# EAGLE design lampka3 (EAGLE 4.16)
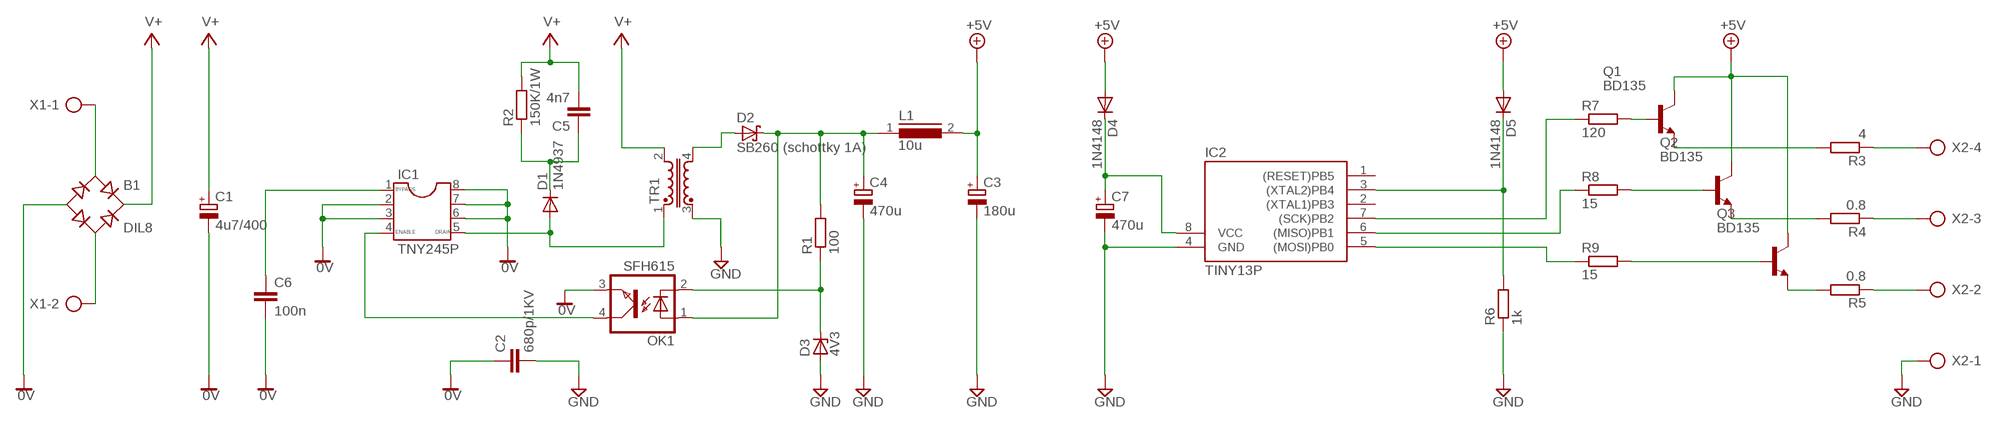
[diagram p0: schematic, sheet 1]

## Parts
B1  DIL8  B-DIL  [B-DIL]
C1  4u7/400  CPOL-EUE5-10.5  [E5-10,5]
C2  680p/1KV  C-EU102-043X133  [C102-043X133]
C3  180u  CPOL-EUE2.5-6  [E2,5-6]
C4  470u  CPOL-EUE3.5-8  [E3,5-8]
C5  4n7  C-EU050-025X075  [C050-025X075]
C6  100n  C-EU050-024X044  [C050-024X044]
C7  470u  CPOL-EUE2.5-7  [E2,5-7]
D1  1N4937  1N4933  [DO41-10]
D2  SB260 (schottky 1A)  SCHOTTKY-DIODEF126Z12  [F126Z12]
D3  4V3  ZENER-DIODEDO35Z10  [DO35Z10]
D4  1N4148  [DO35-10]
D5  1N4148  [DO35-10]
IC1  TNY245P  DIL8  [DIL08]
IC2  TINY13P  TINY12P  [DIL08]
L1  10u  82114R  [82114R]
OK1  SFH615  [DIL04]
Q1  BD135  BD139  [TO126]
Q2  BD135  BD139  [TO126]
Q3  BD135  BD139  [TO126]
R1  100  R-EU_0207/10  [0207/10]
R2  150K/1W  R-EU_0411/12  [0411/12]
R3  4  R-EU_0411/12  [0411/12]
R4  0.8  R-EU_0411/12  [0411/12]
R5  0.8  R-EU_0411/12  [0411/12]
R6  1k  R-EU_0207/10  [0207/10]
R7  120  R-EU_0207/10  [0207/10]
R8  15  R-EU_0207/10  [0207/10]
R9  15  R-EU_0207/10  [0207/10]
TR1  U15-TRANSFORMER  [U15]
X1  AK500/2  [AK500/2]
X2  AK500/4  [AK500/4]

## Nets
0V: B1.- C1.- C2.1 C6.2 IC1.2 IC1.3 IC1.6 IC1.7 IC1.8 OK1.3(EMIT)
+5V: C3.+ D4.A D5.A L1.2 Q1.2(C) Q2.2(C) Q3.2(C)
GND: C2.2 C3.- C4.- C7.- D3.A IC2.4(GND) R6.1 TR1.3 X2.1
N$1: B1.AC1 X1.1
N$2: B1.AC2 X1.2
N$3: C6.1 IC1.1
N$4: IC1.4 OK1.4(COL)
N$5: D1.A IC1.5 TR1.1
N$6: C5.1 D1.C R2.1
N$7: D2.A TR1.4
N$8: C4.+ D2.C L1.1 OK1.1(A) R1.2
N$9: D3.C OK1.2(C) R1.1
N$11: D5.C IC2.3((XTAL2)PB4) R6.2
N$12: IC2.5((MOSI)PB0) R9.1
N$13: IC2.6((MISO)PB1) R8.1
N$14: IC2.7((SCK)PB2) R7.1
N$15: Q1.3(B) R7.2
N$16: Q2.3(B) R8.2
N$17: Q3.3(B) R9.2
N$19: R5.1 X2.2
N$20: Q1.1(E) R3.2
N$21: Q2.1(E) R4.2
N$22: Q3.1(E) R5.2
N$23: C7.+ D4.C IC2.8(VCC)
N$24: R4.1 X2.3
N$25: R3.1 X2.4
V+: B1.+ C1.+ C5.2 R2.2 TR1.2
Unconnected: IC2.1((RESET)PB5) IC2.2((XTAL1)PB3)

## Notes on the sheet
- BYPASS
- ENABLE | DRAIN

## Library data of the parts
B1 = rectifier:B-DIL: RECTIFIER
C1 C3 C4 C7 = rcl:CPOL-EU: POLARIZED CAPACITOR, European symbol
C2 C5 C6 = rcl:C-EU: CAPACITOR, European symbol
D1 = diode:1N4933: DIODE
D2 = diode:SCHOTTKY-DIODE: Schottky Diode
D3 = diode:ZENER-DIODE: Z-Diode
D4 D5 = diode:1N4148: DIODE
IC1 = ic-package:DIL8: Dual In Line
IC2 = atmel:TINY12*: MICROCONTROLLER 1 Kbytes FLASH 64 bytes EEPROM
L1 = inductors:82114R: INDUCTOR
OK1 = optocoupler:SFH615: SIEMENS OPTO COUPLER
Q1-Q3 = transistor-npn:BD139*: NPN Transistor
R1-R9 = rcl:R-EU_: RESISTOR, European symbol
TR1 = inductor-neosid2:U15: TRANSFORMER U15
X1 = con-ptr500:AK500/2: CONNECTOR
X2 = con-ptr500:AK500/4: CONNECTOR

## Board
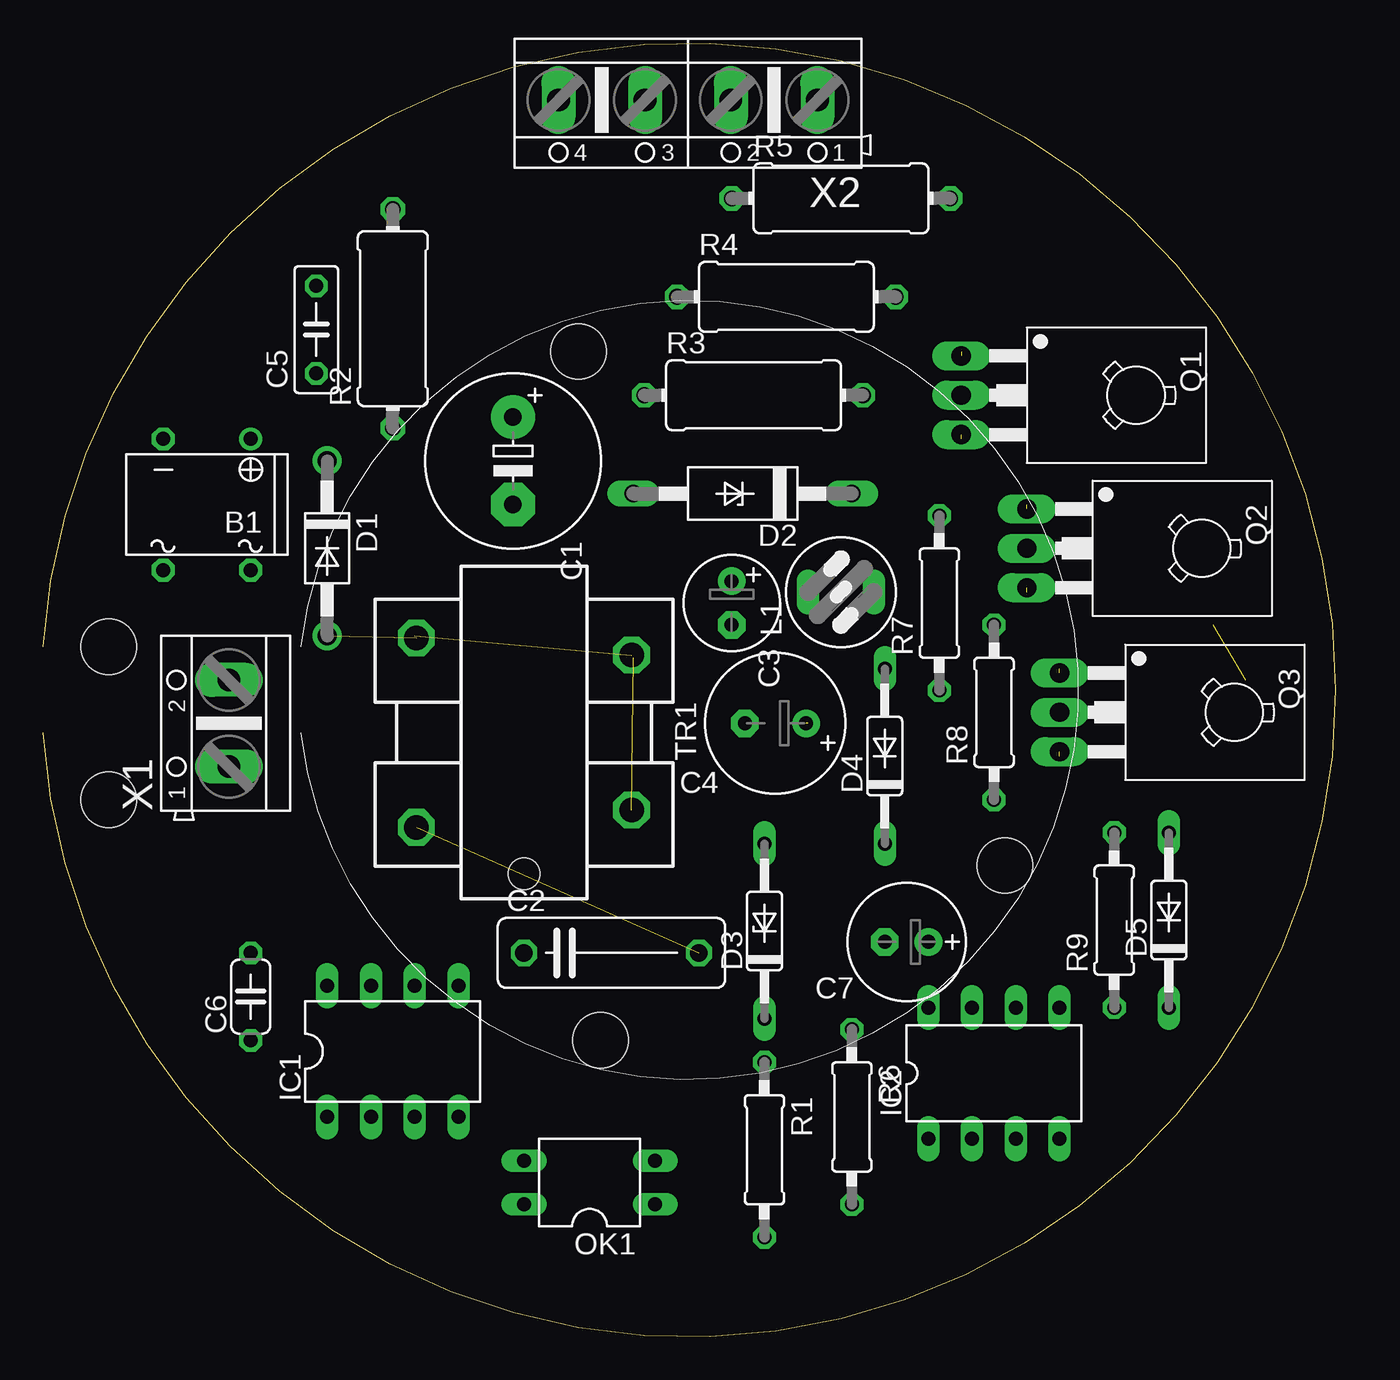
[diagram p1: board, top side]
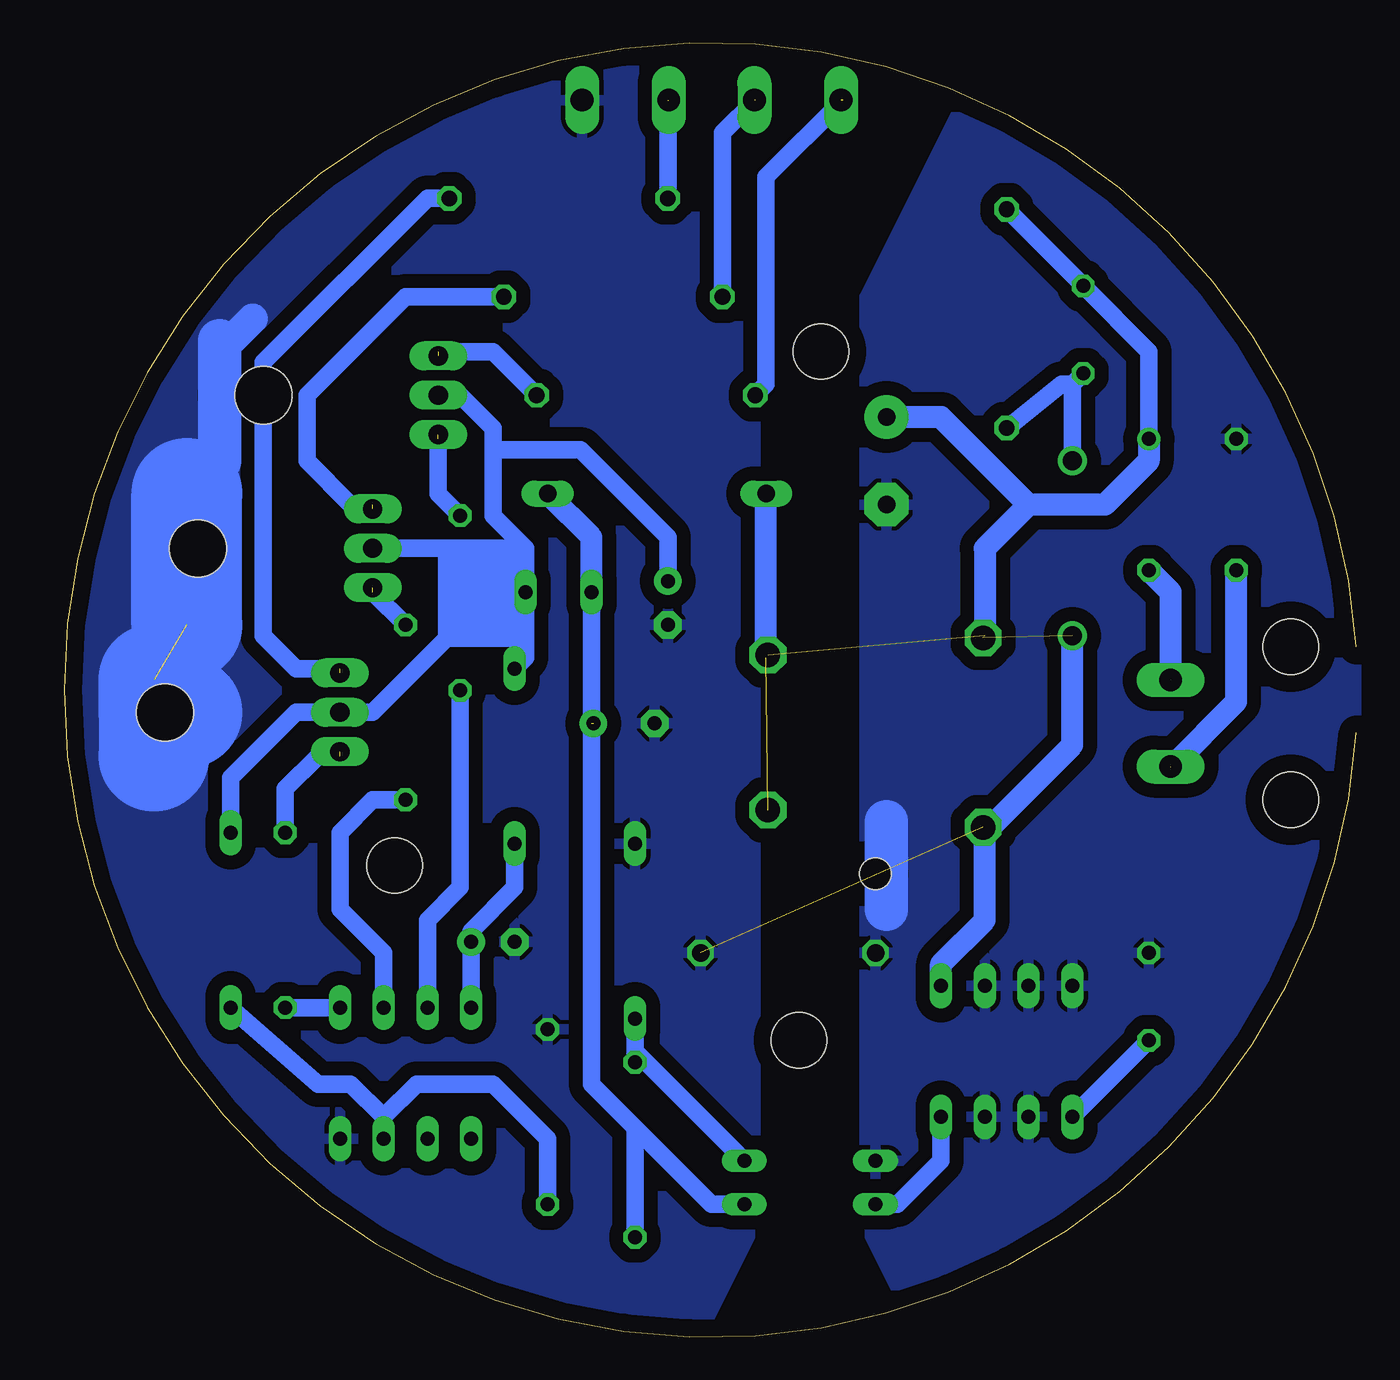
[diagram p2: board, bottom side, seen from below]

Size 75.08 x 75.13 mm. Coordinates in mm from the lower left corner, seen from the top.
Outline: 0,40.06 arc-352 0,35.06
Copper layers (1*16): Top 0.035mm / dielectric 1.5mm / Bottom 0.035mm
Design rules "default": minimum track width 10mil, minimum drill 24mil, track to track 32mil, track to pad 32mil, pad to pad 32mil, via to via 32mil, smd to smd 32mil, copper to edge 40mil, drill to drill 8mil, minimum pad ring 10mil, minimum via ring 8mil, stop-mask expansion 4mil, vias tented up to drill 0mil, thermal gap 10mil
Holes 3.2 mm at 3.81,40.07 3.81,31.18 31.11,57.21 32.38,17.21 55.88,27.37

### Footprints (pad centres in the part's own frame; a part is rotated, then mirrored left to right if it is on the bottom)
B-DIL = drill 0.813 round: + -2.54,-3.81 | drill 0.813 octagon: - 2.54,-3.81; AC1 2.54,3.81; AC2 -2.54,3.81
E5-10,5 = drill 1.016 pad 2.54 round: + -2.54,0 | drill 1.016 pad 2.54 octagon: - 2.54,0
C102-043X133 = drill 1.016 octagon: 1 -5.08,0; 2 5.08,0
E2,5-6 = drill 0.813 pad 1.6 round: + -1.27,0 | drill 0.813 pad 1.6 octagon: - 1.27,0
E3,5-8 = drill 0.813 pad 1.6 round: + -1.778,0 | drill 0.813 pad 1.6 octagon: - 1.778,0
C050-025X075 = drill 0.813 octagon: 1 -2.54,0; 2 2.54,0
C050-024X044 = drill 0.813 octagon: 1 -2.54,0; 2 2.54,0
E2,5-7 = drill 0.813 pad 1.6 round: + -1.27,0 | drill 0.813 pad 1.6 octagon: - 1.27,0
DO41-10 = drill 1.118 round: A 5.08,0; C -5.08,0
F126Z12 = drill 1.016 long: A 6.35,0; C -6.35,0
DO35Z10 = drill 0.813 long: A 5.08,0; C -5.08,0
DO35-10 = drill 0.813 long: A 5.08,0; C -5.08,0
DIL08 = drill 0.813 long: 1 -3.81,-3.81; 2 -1.27,-3.81; 3 1.27,-3.81; 4 3.81,-3.81; 5 3.81,3.81; 6 1.27,3.81; 7 -1.27,3.81; 8 -3.81,3.81
82114R = drill 0.813 long: 1 0,1.905; 2 0,-1.905
DIL04 = drill 0.813 long: 1 -1.27,-3.81; 2 1.27,-3.81; 3 1.27,3.81; 4 -1.27,3.81
TO126 = drill 1.118 long: 1 -2.286,-5.08; 2 0,-5.08; 3 2.286,-5.08 | hole 3.302: 0,5.08
0207/10 = drill 0.813 octagon: 1 -5.08,0; 2 5.08,0
0411/12 = drill 0.914 octagon: 1 -6.35,0; 2 6.35,0
U15 = drill 1.422 octagon: 1 -7.5,-6.25; 2 -6.5,6.25; 3 3.5,-6.25; 4 2.5,6.25 | hole 1.8: 6.2,0
AK500/2 = drill 1.321 long: 1 -2.515,0; 2 2.515,0
AK500/4 = drill 1.321 long: 1 -7.518,0; 2 -2.489,0; 3 2.489,0; 4 7.518,0

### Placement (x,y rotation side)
B1  9.53,48.32 180 top
C1  27.3,50.86 270 top
C2  33.02,22.29 0 top
C3  40.01,42.61 270 top
C4  42.55,35.62 180 top
C5  15.88,58.48 90 top
C6  12.06,19.75 90 top
C7  50.16,22.92 180 top
D1  16.51,45.78 270 top
D2  40.64,48.96 180 top
D3  41.91,23.56 90 top
D4  48.9,33.72 90 top
D5  65.41,24.19 90 top
IC1  20.32,16.57 0 top
IC2  55.24,15.3 0 top
L1  46.35,43.24 90 top
OK1  31.75,8.95 90 top
Q1  58.42,54.67 270 top
Q2  62.23,45.78 270 top
Q3  64.14,36.26 270 top
R1  41.91,10.86 270 top
R2  20.32,59.12 90 top
R3  41.27,54.67 0 top
R4  43.18,60.39 0 top
R5  46.35,66.1 0 top
R6  46.99,12.76 270 top
R7  52.07,42.61 90 top
R8  55.24,36.26 90 top
R9  62.23,24.19 90 top
TR1  27.94,33.08 270 top
X1  10.79,35.62 90 top
X2  37.47,71.82 180 top

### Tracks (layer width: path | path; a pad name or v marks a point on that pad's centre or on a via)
0V
  Bottom 2.54: 27.3,24.83 27.3,29.91
  pour Bottom: 28.57,60.39 28.57,6.41 25.4,0.06 0,0.06 0,73.09 22.23,73.09
+5V
  Bottom 1.016: Q1.2 52.07,54.67 50.16,52.77 50.16,51.5 | 50.16,51.5 50.16,47.69 48.26,45.78 | 48.26,45.78 L1.2 48.26,39.43 D4.A | 48.26,45.78 52.07,45.78 | 52.07,45.78 Q2.2 | 50.16,51.5 45.09,51.5 40.01,46.42 C3.+ | 52.07,45.78 52.07,41.34 57.15,36.26 Q3.2 61.59,36.26 65.41,32.45 D5.A
GND  (2 unrouted)
  Bottom 1.778: 65.41,57.85 64.14,59.12
  Bottom 2.54: 66.04,50.86 66.04,57.85
  Bottom 6.452: 69.85,36.26 69.85,33.72 | 69.85,36.26 69.85,38.16 | 67.94,36.26 69.85,36.26 | 67.94,41.34 67.94,48.96
  pour Bottom: 34.92,76.26 76.2,76.26 76.2,0.06 38.1,0.06 34.92,6.41
N$1  (1 unrouted)
  Bottom 1.27: 10.79,33.08 6.99,36.89 B1.AC1
N$2  (1 unrouted)
  Bottom 1.27: 10.79,38.16 10.79,43.24 B1.AC2
N$3
  Bottom 1.016: C6.1 IC1.1
N$4
  Bottom 1.016: IC1.4 24.13,10.22 26.67,7.68 OK1.4
N$5  (1 unrouted)
  Bottom 1.27: D1.A 16.51,34.35 21.59,29.27 21.59,24.19 24.13,21.65 IC1.5
N$6
  Bottom 1.016: 16.51,55.31 17.14,55.31 R2.1 | 16.51,55.31 C5.1 | D1.C 16.51,55.31
N$7  (1 unrouted)
  Bottom 1.27: 34.29,39.43 D2.A
N$8  (1 unrouted)
  Bottom 1.016: L1.1 44.45,35.62 44.45,14.67 41.91,12.13 | 41.91,12.13 37.47,7.68 OK1.1 | 41.91,12.13 R1.2
  Bottom 1.27: D2.C 44.45,46.42 L1.1
N$9
  Bottom 1.016: OK1.2 41.91,16.57 | 41.91,16.57 D3.C | 41.91,16.57 R1.1
N$11
  Bottom 1.016: R6.2 46.99,11.49 50.16,14.67 54.61,14.67 56.52,12.76 | 56.52,12.76 IC2.3 | 56.52,12.76 58.42,14.67 60.33,14.67 D5.C
N$12
  Bottom 1.016: IC2.5 R9.1
N$13
  Bottom 1.016: R8.1 57.15,31.18 59.05,29.27 59.05,24.83 56.52,22.29 IC2.6
N$14
  Bottom 1.016: R7.1 52.07,26.1 53.98,24.19 IC2.7
N$15  (1 unrouted)
  Bottom 1.016: R7.2 53.34,48.96 53.34,52.13
N$16  (1 unrouted)
  Bottom 1.016: R8.2 57.15,43.24
N$17  (1 unrouted)
  Bottom 1.016: R9.2 62.23,31.81 60.33,33.72 59.05,33.72
N$19  (1 unrouted)
  Bottom 1.016: R5.1 40.01,71.82
N$20  (1 unrouted)
  Bottom 1.016: R3.2 50.16,57.21 53.34,57.21
N$21  (1 unrouted)
  Bottom 1.016: R4.2 55.24,60.39 60.96,54.67 60.96,50.86 58.42,48.32 57.15,48.32
N$22  (1 unrouted)
  Bottom 1.016: R5.2 53.98,66.1 63.5,56.58 63.5,40.7 61.59,38.8 59.05,38.8
N$23
  Bottom 1.016: D4.C 48.9,26.1 51.44,23.56 C7.+ IC2.8
N$24  (1 unrouted)
  Bottom 1.016: 34.92,71.82 36.83,69.91 R4.1
N$25  (1 unrouted)
  Bottom 1.016: 29.84,71.82 34.29,67.37 34.29,55.31 R3.1
V+  (1 unrouted)
  Bottom 1.016: R2.2 C5.2 12.06,57.21 B1.+
  Bottom 1.27: B1.+ 12.06,50.86 14.61,48.32 19.05,48.32 | 19.05,48.32 21.59,45.78 21.59,40.7 | C1.+ 24.13,53.4 19.05,48.32
(copper drawn outside any net)
  shapes: Bottom area x1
